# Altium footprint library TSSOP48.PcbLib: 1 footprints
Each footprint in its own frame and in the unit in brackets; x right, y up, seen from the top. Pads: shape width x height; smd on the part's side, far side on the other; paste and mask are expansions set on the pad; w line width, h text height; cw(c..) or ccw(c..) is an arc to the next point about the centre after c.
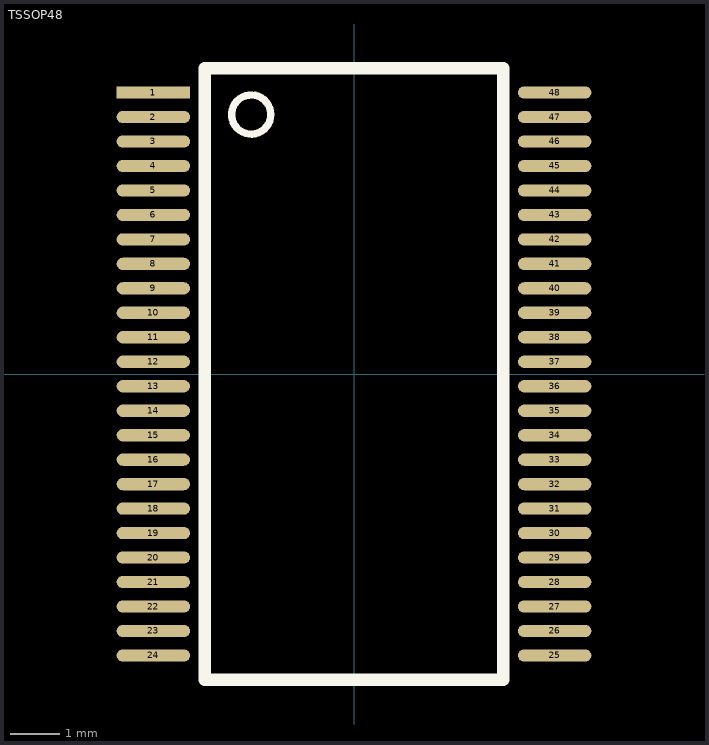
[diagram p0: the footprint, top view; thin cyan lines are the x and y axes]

## TSSOP48 [mm]
pads (48):
  rect 1.5x0.25 smd: 1(-4.1,5.75)
  oval 1.5x0.25 smd: 2(-4.1,5.25) 3(-4.1,4.75) 4(-4.1,4.25) 5(-4.1,3.75) 6(-4.1,3.25) 7(-4.1,2.75) 8(-4.1,2.25) 9(-4.1,1.75) 10(-4.1,1.25) 11(-4.1,0.75) 12(-4.1,0.25) 13(-4.1,-0.25) 14(-4.1,-0.75) 15(-4.1,-1.25) 16(-4.1,-1.75) 17(-4.1,-2.25) 18(-4.1,-2.75) 19(-4.1,-3.25) 20(-4.1,-3.75) 21(-4.1,-4.25) 22(-4.1,-4.75) 23(-4.1,-5.25) 24(-4.1,-5.75) 25(4.1,-5.75) 26(4.1,-5.25) 27(4.1,-4.75) 28(4.1,-4.25) 29(4.1,-3.75) 30(4.1,-3.25) 31(4.1,-2.75) 32(4.1,-2.25) 33(4.1,-1.75) 34(4.1,-1.25) 35(4.1,-0.75) 36(4.1,-0.25) 37(4.1,0.25) 38(4.1,0.75) 39(4.1,1.25) 40(4.1,1.75) 41(4.1,2.25) 42(4.1,2.75) 43(4.1,3.25) 44(4.1,3.75) 45(4.1,4.25) 46(4.1,4.75) 47(4.1,5.25) 48(4.1,5.75)
Top Overlay:
  circle w0.15: c-2.1,5.3 r0.4
  lines w0.254: -3.05,-6.25 3.05,-6.25 3.05,6.25 -3.05,6.25 -3.05,-6.25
